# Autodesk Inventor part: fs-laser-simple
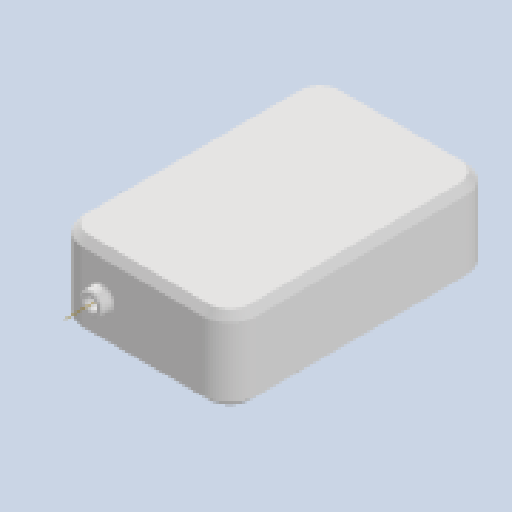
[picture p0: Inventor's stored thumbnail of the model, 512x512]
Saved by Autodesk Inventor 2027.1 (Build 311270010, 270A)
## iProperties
Created: 2026-07
Part Number: fs-laser-simple
Material: Generic
Document SubType Name: Modeling
Designer: dunge
Density: 1 g/cm^3
Appearance: Default
Author: dunge
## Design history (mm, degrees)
sketch "Sketch1"
  geometry: L1 (21.316, -5.227)-(-58.758, -5.227); L2 (-58.758, -5.227)-(-58.758, -126.76); L3 (-58.758, -126.76)-(21.316, -126.76); L4 (21.316, -126.76)-(21.316, -5.227); L5 (2.54, 0)-(5.08, 0); L6 (5.08, 0)-(5.08, -5.227); L7 (5.08, -5.227)-(2.54, -5.227); L8 (2.54, -5.227)-(2.54, 0); L9 (0, 0)-(0, -5.227); 1 further point
  constraints: 18 end point, 4 parallel, 3 perpendicular, 2 horizontal, 2 point on line, 1 horizontal alignment
  dimensions: "d0" = 2.54 distance between parallel lines of L9 L8; "d1" = 2.54 distance between parallel lines of L8 L6
extrude "Extrusion1" new body sketch "Sketch1" stored distance "d2" = 38.1; taper "d3" = 0 deg
revolve "Revolution1" stored, may be unused: angle "d4" = 90 deg
workaxis "Work Axis1"
workpoint "Work Point1"
fillet "Fillet1" dims "d5" = 12.7
chamfer "Chamfer1" distance "d6" = 3.175; stored, may be unused: second distance "d7" = 3.175, angle "d8" = 45 deg
chamfer "Chamfer2" distance "d9" = 0.635; stored, may be unused: second distance "d10" = 3.175, angle "d11" = 45 deg
body "Solid1"
